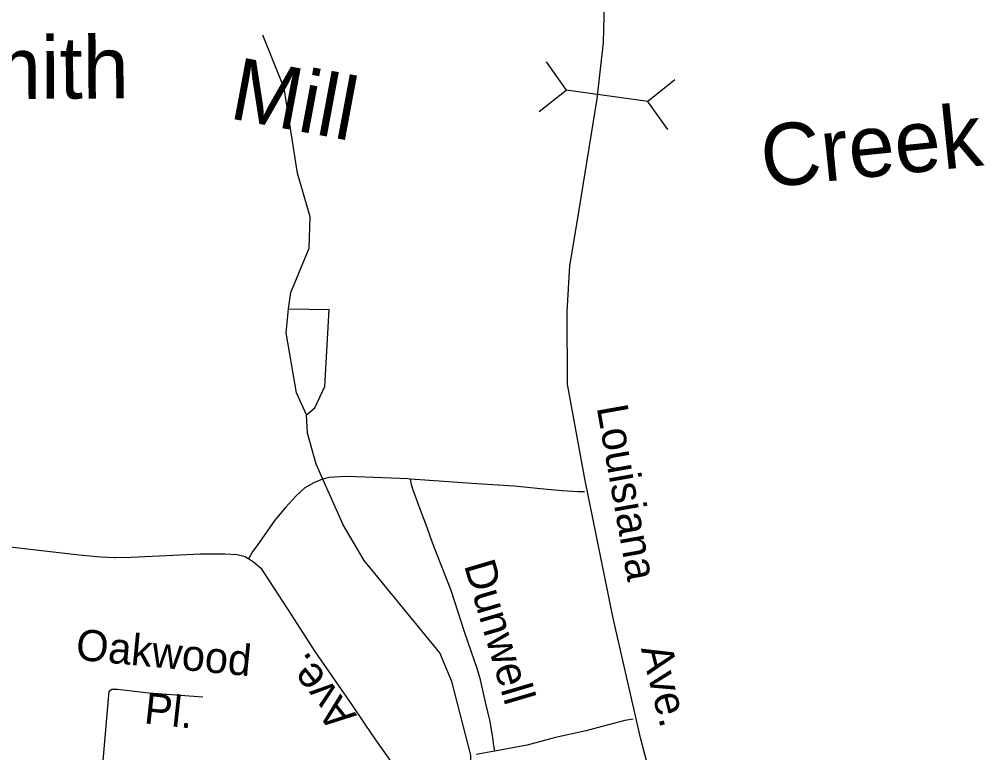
# Model space of a CAD drawing. Extents: x 925297 to 940193, y 663541 to 689899.
# Drawn here: x 928270.8 to 928734.3, y 688368 to 688721.9 of the extents above; entities that cross this region are included whole.
import ezdxf

# ---------------------------------------------------------------- set-up
doc = ezdxf.new("R2010")
doc.units = 0
doc.layers.add('Default', color=7, linetype='Continuous')

msp = doc.modelspace()

# ---------------------------------------------------------------- linework, layer by layer
at = {"layer": 'Default'}
for p, q in [((928525.15, 688701.36), (928534.8, 688687.78)), ((928587.12, 688692.62), (928574.09, 688682.25)), ((928521.78, 688677.41), (928534.8, 688687.78)), ((928574.09, 688682.25), (928534.8, 688687.78)), ((928583.75, 688668.67), (928574.09, 688682.25)), ((928400.82, 688582.16), (928420.43, 688581.84))]:
    msp.add_line(p, q, dxfattribs=at)
for points in [[(928549.65, 688683.45), (928552.82, 688710.77), (928553.42, 688736.09)], [(928400.82, 688582.16), (928401.91, 688590.12), (928410.69, 688611.42), (928411.24, 688626.6), (928405.17, 688647.64), (928398.65, 688688.7), (928388.45, 688714.29)], [(928639.49, 688117.35), (928636.74, 688129.36), (928605.26, 688245.37), (928596.11, 688280.14), (928587.03, 688313.06), (928570.72, 688374.57), (928557.39, 688432.9), (928543.73, 688500.18), (928535.46, 688545.84), (928535.24, 688580.9), (928536.47, 688602.87), (928540.02, 688623.94), (928549.65, 688683.45)], [(928409.41, 688531.01), (928404.58, 688541.59), (928399.61, 688570.59), (928400.82, 688582.16)], [(928409.41, 688531.01), (928413.54, 688534.47), (928418.31, 688544.7), (928420.43, 688581.84)], [(928491.23, 688323.13), (928488.24, 688340.05), (928488.77, 688366.85), (928479.65, 688402.41), (928473.74, 688416.23), (928437.3, 688460.76), (928427.13, 688477.94), (928414.15, 688507.23), (928409.89, 688522.18), (928409.41, 688531.01)], [(928459.57, 688500.04), (928458.34, 688500.12), (928442.27, 688500.8), (928428.38, 688501.25), (928420.24, 688500.75), (928416.37, 688499.65), (928413.03, 688498.26), (928408.72, 688495.77), (928404.57, 688492.12), (928399.37, 688486.36), (928394.21, 688480.13), (928385.68, 688468.06), (928383.5, 688465.23), (928381.45, 688461.56)], [(928543.56, 688493.9), (928540.47, 688493.88), (928532.82, 688494.28), (928523.93, 688495.12), (928509.63, 688496.57), (928499.39, 688497.24), (928489.31, 688497.96), (928475.74, 688498.93), (928459.57, 688500.04)], [(928500.33, 688368.78), (928499.65, 688372.49), (928499.55, 688374.22), (928498.02, 688382.99), (928495.83, 688392.36), (928494.53, 688398.16), (928493.41, 688403.22), (928491.75, 688408.56), (928489.04, 688416.47), (928485.65, 688426.28), (928482.56, 688435.74), (928479.24, 688446.25), (928476.43, 688453.68), (928472.88, 688462.69), (928470.28, 688469.23), (928467.81, 688476.26), (928464.28, 688485.59), (928460.84, 688495.12), (928460.13, 688497.35), (928459.57, 688500.04)], [(928199.76, 688475.04), (928225.92, 688471.99), (928249.06, 688469.18), (928262.31, 688467.87), (928283.08, 688465.39), (928299.83, 688463.53), (928310.21, 688462.45), (928316.79, 688462.13), (928317.29, 688462.15)], [(928317.29, 688462.15), (928324.89, 688462.41), (928341.78, 688463.12), (928358.28, 688463.98), (928370.05, 688463.96), (928376.01, 688463.62), (928379.86, 688462.6), (928381.45, 688461.56)], [(928450.39, 688363.67), (928441.85, 688375.8), (928431.84, 688390.56), (928413.67, 688416.77), (928400.64, 688437.16), (928391.23, 688451.37), (928387.84, 688456.51), (928383.92, 688459.95), (928381.45, 688461.56)], [(928299.14, 688211.61), (928299.1, 688221.85), (928300.01, 688233.15), (928300.68, 688240.97), (928314.23, 688397.68), (928315.47, 688398.63), (928318.24, 688398.62), (928333.4, 688396.95), (928359.48, 688394.88)], [(928567.13, 688384.15), (928563.08, 688383.61), (928544.23, 688378.55), (928529.62, 688375.37), (928515.88, 688371.68), (928500.33, 688368.78)], [(928500.33, 688368.78), (928498.4, 688368.42), (928491.29, 688367.12)]]:
    msp.add_lwpolyline(points, dxfattribs=at)

# ---------------------------------------------------------------- texts
for s, height, rotation, p in [('Smith', 30, 0.366, (928221.29, 688683.13)), ('Mill', 30, 349.4068, (928371.52, 688674.25)), ('Creek', 30, 5.8579, (928630.17, 688640.53)), ('Louisiana', 15, 280.0837, (928549.42, 688534.7)), ('Dunwell', 15, 286.4411, (928485.36, 688458.51)), ('Oakwood', 15, 354.5444, (928297.74, 688412.93)), ('Ave.', 15, 284.0547, (928570.76, 688418.26)), ('Ave.', 15, 128.2244, (928433.99, 688386.08)), ('Pl.', 15, 353.7025, (928330.68, 688382.23))]:
    msp.add_text(s, height=height, rotation=rotation, dxfattribs=at).set_placement(p)

doc.saveas('drawing.dxf')
